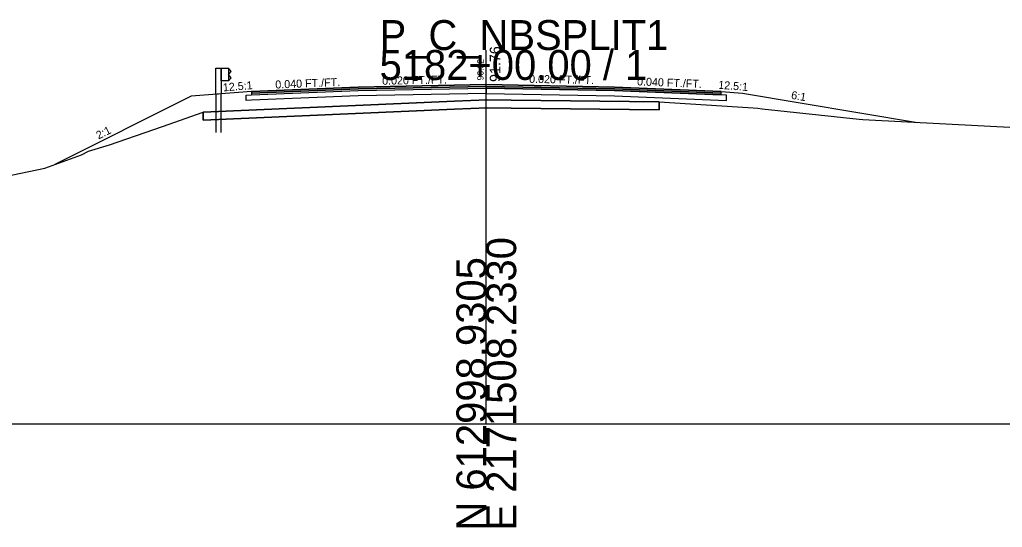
# Model space of a CAD drawing. Extents: x -26 to 1303, y -3010 to 12038.
# Drawn here: x 106.3 to 198.4, y 4490.3 to 4537.8 of the extents above; entities that cross this region are included whole.
import ezdxf

# ---------------------------------------------------------------- set-up
doc = ezdxf.new("R2010")
doc.units = 0
for name, color, linetype in [('RD_GPK_XS_Cell', 7, 'Continuous'), ('RD_PD_Final_TrvlWay', 7, 'Continuous'), ('RD_XS_Base', 7, 'Continuous'), ('RD_XS_ExGround', 7, 'Continuous'), ('RD_XS_ExPaveRet', 7, 'Continuous'), ('RD_XS_GR', 7, 'Continuous'), ('RD_XS_Greenside', 7, 'Continuous'), ('RD_XS_Pave', 7, 'Continuous'), ('RD_XS_PaveOvlay_CP', 7, 'Continuous'), ('RD_XS_TieSlope', 7, 'Continuous'), ('RD_XS_TX_Elev_EX', 7, 'Continuous'), ('RD_XS_TX_Elev_PR', 7, 'Continuous'), ('RD_XS_TX_ShdSlope', 7, 'Continuous'), ('RD_XS_TX_Slope', 7, 'Continuous')]:
    doc.layers.add(name, color=color, linetype=linetype)

msp = doc.modelspace()

# ---------------------------------------------------------------- linework, layer by layer
at = {"layer": 'RD_GPK_XS_Cell'}
for p, q in [((150, 4500), (150, 4535)), ((0, 4500), (150, 4500)), ((150, 4500), (300, 4500))]:
    msp.add_line(p, q, dxfattribs=at)
at = {"layer": 'RD_PD_Final_TrvlWay'}
for p, q in [((125.167, 4530.89), (124.667, 4530.85)), ((125.167, 4527.285), (125.167, 4530.89)), ((124.667, 4530.85), (124.667, 4527.285))]:
    msp.add_line(p, q, dxfattribs=at)
at = {"layer": 'RD_XS_Base'}
for p, q in [((128, 4530.799), (138, 4531.199)), ((138, 4531.199), (150, 4531.439)), ((138, 4531.199), (138, 4531.199)), ((150, 4530.939), (138, 4530.699)), ((150, 4531.439), (150, 4531.598)), ((150, 4531.598), (150, 4530.939)), ((150, 4531.439), (150, 4530.939)), ((162, 4531.199), (150, 4531.439)), ((150, 4531.439), (150, 4531.439)), ((150, 4530.939), (150, 4530.939)), ((150, 4530.939), (150, 4530.939)), ((150, 4530.939), (162, 4530.699)), ((172, 4530.799), (162, 4531.199)), ((164, 4531.119), (164, 4531.119)), ((127.5, 4530.779), (128, 4530.799)), ((127.5, 4530.279), (127.5, 4530.779)), ((127.5, 4530.779), (127.5, 4530.779)), ((128, 4530.299), (127.5, 4530.279)), ((127.5, 4530.279), (127.5, 4530.279)), ((127.5, 4530.279), (127.5, 4530.279)), ((128, 4530.799), (128, 4530.799)), ((138, 4530.699), (128, 4530.299)), ((128, 4530.299), (128, 4530.299)), ((138, 4530.699), (138, 4530.699)), ((162, 4530.699), (172.5, 4530.279)), ((164, 4530.619), (164, 4530.619)), ((172.5, 4530.779), (172, 4530.799)), ((172, 4530.799), (172, 4530.799)), ((172.5, 4530.279), (172.5, 4530.779)), ((172.5, 4530.779), (172.5, 4530.779)), ((172.5, 4530.279), (172.5, 4530.279)), ((172.5, 4530.279), (172.5, 4530.279))]:
    msp.add_line(p, q, dxfattribs=at)
at = {"layer": 'RD_XS_ExGround'}
msp.add_lwpolyline([(103.36, 4522.845), (108.652, 4523.936), (112.062, 4525.185), (112.74, 4525.541), (114.707, 4526.112), (119.661, 4527.85), (123.488, 4529.178), (147.026, 4530.207), (150.088, 4530.323), (152.326, 4530.295), (166.207, 4530.137), (175.015, 4529.576), (175.452, 4529.549), (175.859, 4529.486), (184.921, 4528.513), (185.277, 4528.495), (200.227, 4527.708)], dxfattribs=at)
at = {"layer": 'RD_XS_ExPaveRet'}
msp.add_line((152.326, 4530.295), (150.088, 4530.323), dxfattribs=at)
for points in [[(166.207, 4530.137), (166.207, 4530.137), (166.207, 4529.387), (166.207, 4529.387), (166.207, 4529.387), (152.326, 4529.545), (152.326, 4529.545), (150.088, 4529.573), (147.026, 4529.457), (147.026, 4529.457), (123.488, 4528.428), (123.488, 4528.428), (123.488, 4529.178), (123.488, 4529.178), (123.488, 4529.178), (147.026, 4530.207), (147.026, 4530.207), (150.088, 4530.323), (152.326, 4530.295), (152.326, 4530.295), (166.207, 4530.137)], [(150.088, 4530.323), (147.026, 4530.207), (123.488, 4529.178)], [(123.488, 4529.178), (123.488, 4528.428), (147.026, 4529.457), (150.088, 4529.573), (152.326, 4529.545), (166.207, 4529.387), (166.207, 4530.137), (152.326, 4530.295)]]:
    msp.add_lwpolyline(points, dxfattribs=at)
at = {"layer": 'RD_XS_GR'}
for points in [[(125.167, 4533.285), (125.167, 4530.89), (124.667, 4530.85), (124.667, 4533.285), (124.917, 4533.285), (125.167, 4533.285)], [(125.834, 4533.285), (125.834, 4532.119), (125.167, 4532.119), (125.167, 4533.285), (125.834, 4533.285)], [(126.105, 4532.994), (125.834, 4533.285), (125.834, 4532.119), (125.834, 4532.119), (125.834, 4532.119), (126.105, 4532.41), (126.105, 4532.41), (125.834, 4532.702), (125.834, 4532.702), (126.105, 4532.994), (126.105, 4532.994)]]:
    msp.add_lwpolyline(points, dxfattribs=at)
at = {"layer": 'RD_XS_Greenside'}
for p, q in [((174, 4530.957), (190.388, 4528.226)), ((122.355, 4530.665), (109.565, 4524.271))]:
    msp.add_line(p, q, dxfattribs=at)
at = {"layer": 'RD_XS_Pave'}
for p, q in [((138, 4531.517), (128, 4531.117)), ((138, 4531.358), (128, 4530.958)), ((128, 4530.958), (138, 4531.358)), ((128, 4530.799), (138, 4531.199)), ((128, 4531.117), (128, 4531.117)), ((128, 4531.117), (128, 4530.958)), ((128, 4530.958), (128, 4530.958)), ((128, 4530.958), (128, 4530.799)), ((128, 4530.958), (128, 4530.958)), ((128, 4530.958), (128, 4530.958)), ((150, 4531.757), (138, 4531.517)), ((150, 4531.598), (138, 4531.358)), ((138, 4531.358), (150, 4531.598)), ((138, 4531.517), (138, 4531.517)), ((138, 4531.199), (150, 4531.439)), ((138, 4531.358), (138, 4531.358)), ((138, 4531.358), (138, 4531.358)), ((138, 4531.199), (138, 4531.199)), ((162, 4531.517), (150, 4531.757)), ((150, 4531.439), (150, 4531.598)), ((150, 4531.598), (162, 4531.358)), ((162, 4531.358), (150, 4531.598)), ((150, 4531.598), (150, 4531.439)), ((150, 4531.439), (150, 4531.439)), ((150, 4531.439), (150, 4531.439)), ((150, 4531.439), (162, 4531.199)), ((172, 4531.117), (162, 4531.517)), ((162, 4531.358), (172, 4530.958)), ((172, 4530.958), (162, 4531.358)), ((162, 4531.199), (172, 4530.799)), ((164, 4531.437), (164, 4531.437)), ((164, 4531.278), (164, 4531.278)), ((164, 4531.278), (164, 4531.278)), ((164, 4531.119), (164, 4531.119)), ((172, 4530.958), (172, 4531.117)), ((172, 4531.117), (172, 4531.117)), ((172, 4530.958), (172, 4530.958)), ((172, 4530.958), (172, 4530.958)), ((172, 4530.799), (172, 4530.958)), ((172, 4530.958), (172, 4530.958)), ((128, 4530.799), (128, 4530.799)), ((128, 4530.799), (128, 4530.799)), ((172, 4530.799), (172, 4530.799)), ((172, 4530.799), (172, 4530.799))]:
    msp.add_line(p, q, dxfattribs=at)
at = {"layer": 'RD_XS_PaveOvlay_CP'}
for p, q in [((128, 4531.117), (138, 4531.517)), ((138, 4531.517), (150, 4531.757)), ((150, 4531.757), (162, 4531.517)), ((162, 4531.517), (172, 4531.117))]:
    msp.add_line(p, q, dxfattribs=at)
at = {"layer": 'RD_XS_TieSlope'}
for p, q in [((128, 4531.117), (122.355, 4530.665)), ((172, 4531.117), (174, 4530.957))]:
    msp.add_line(p, q, dxfattribs=at)

# ---------------------------------------------------------------- texts
at = {"layer": 'RD_GPK_XS_Cell'}
for s, p in [('P_C_NBSPLIT1', (140, 4535)), ('5182+00.00 / 1', (140, 4532.2))]:
    msp.add_text(s, height=2.8, dxfattribs=at).set_placement(p)
for s, p in [('E 2171508.2330', (152.8, 4490)), ('N 612998.9305', (150, 4490))]:
    msp.add_text(s, height=2.8, rotation=90, dxfattribs=at).set_placement(p)
at = {"layer": 'RD_XS_TX_Elev_EX'}
msp.add_text('90.32', height=0.6, rotation=90, dxfattribs=at).set_placement((149.744, 4532.157))
at = {"layer": 'RD_XS_TX_Elev_PR'}
msp.add_text('91.76', height=1, rotation=90, dxfattribs=at).set_placement((151.327, 4532.007))
at = {"layer": 'RD_XS_TX_ShdSlope'}
for rotation, p in [(4.57392, (125.35, 4531.12)), (355.42608, (171.711, 4531.381))]:
    msp.add_text('12.5:1', height=0.75, rotation=rotation, dxfattribs=at).set_placement(p)
at = {"layer": 'RD_XS_TX_Slope'}
for s, rotation, p in [('0.040 FT./FT.', 2.29061, (130.247, 4531.39)), ('0.020 FT./FT.', 1.14576, (140.248, 4531.745)), ('0.020 FT./FT.', 358.85424, (154.007, 4531.929)), ('0.040 FT./FT.', 357.70939, (164.115, 4531.691)), ('6:1', 350.53768, (178.524, 4530.434)), ('2:1', 26.56505, (113.668, 4526.621))]:
    msp.add_text(s, height=0.75, rotation=rotation, dxfattribs=at).set_placement(p)

doc.saveas('drawing.dxf')
